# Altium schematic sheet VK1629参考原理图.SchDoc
size A3
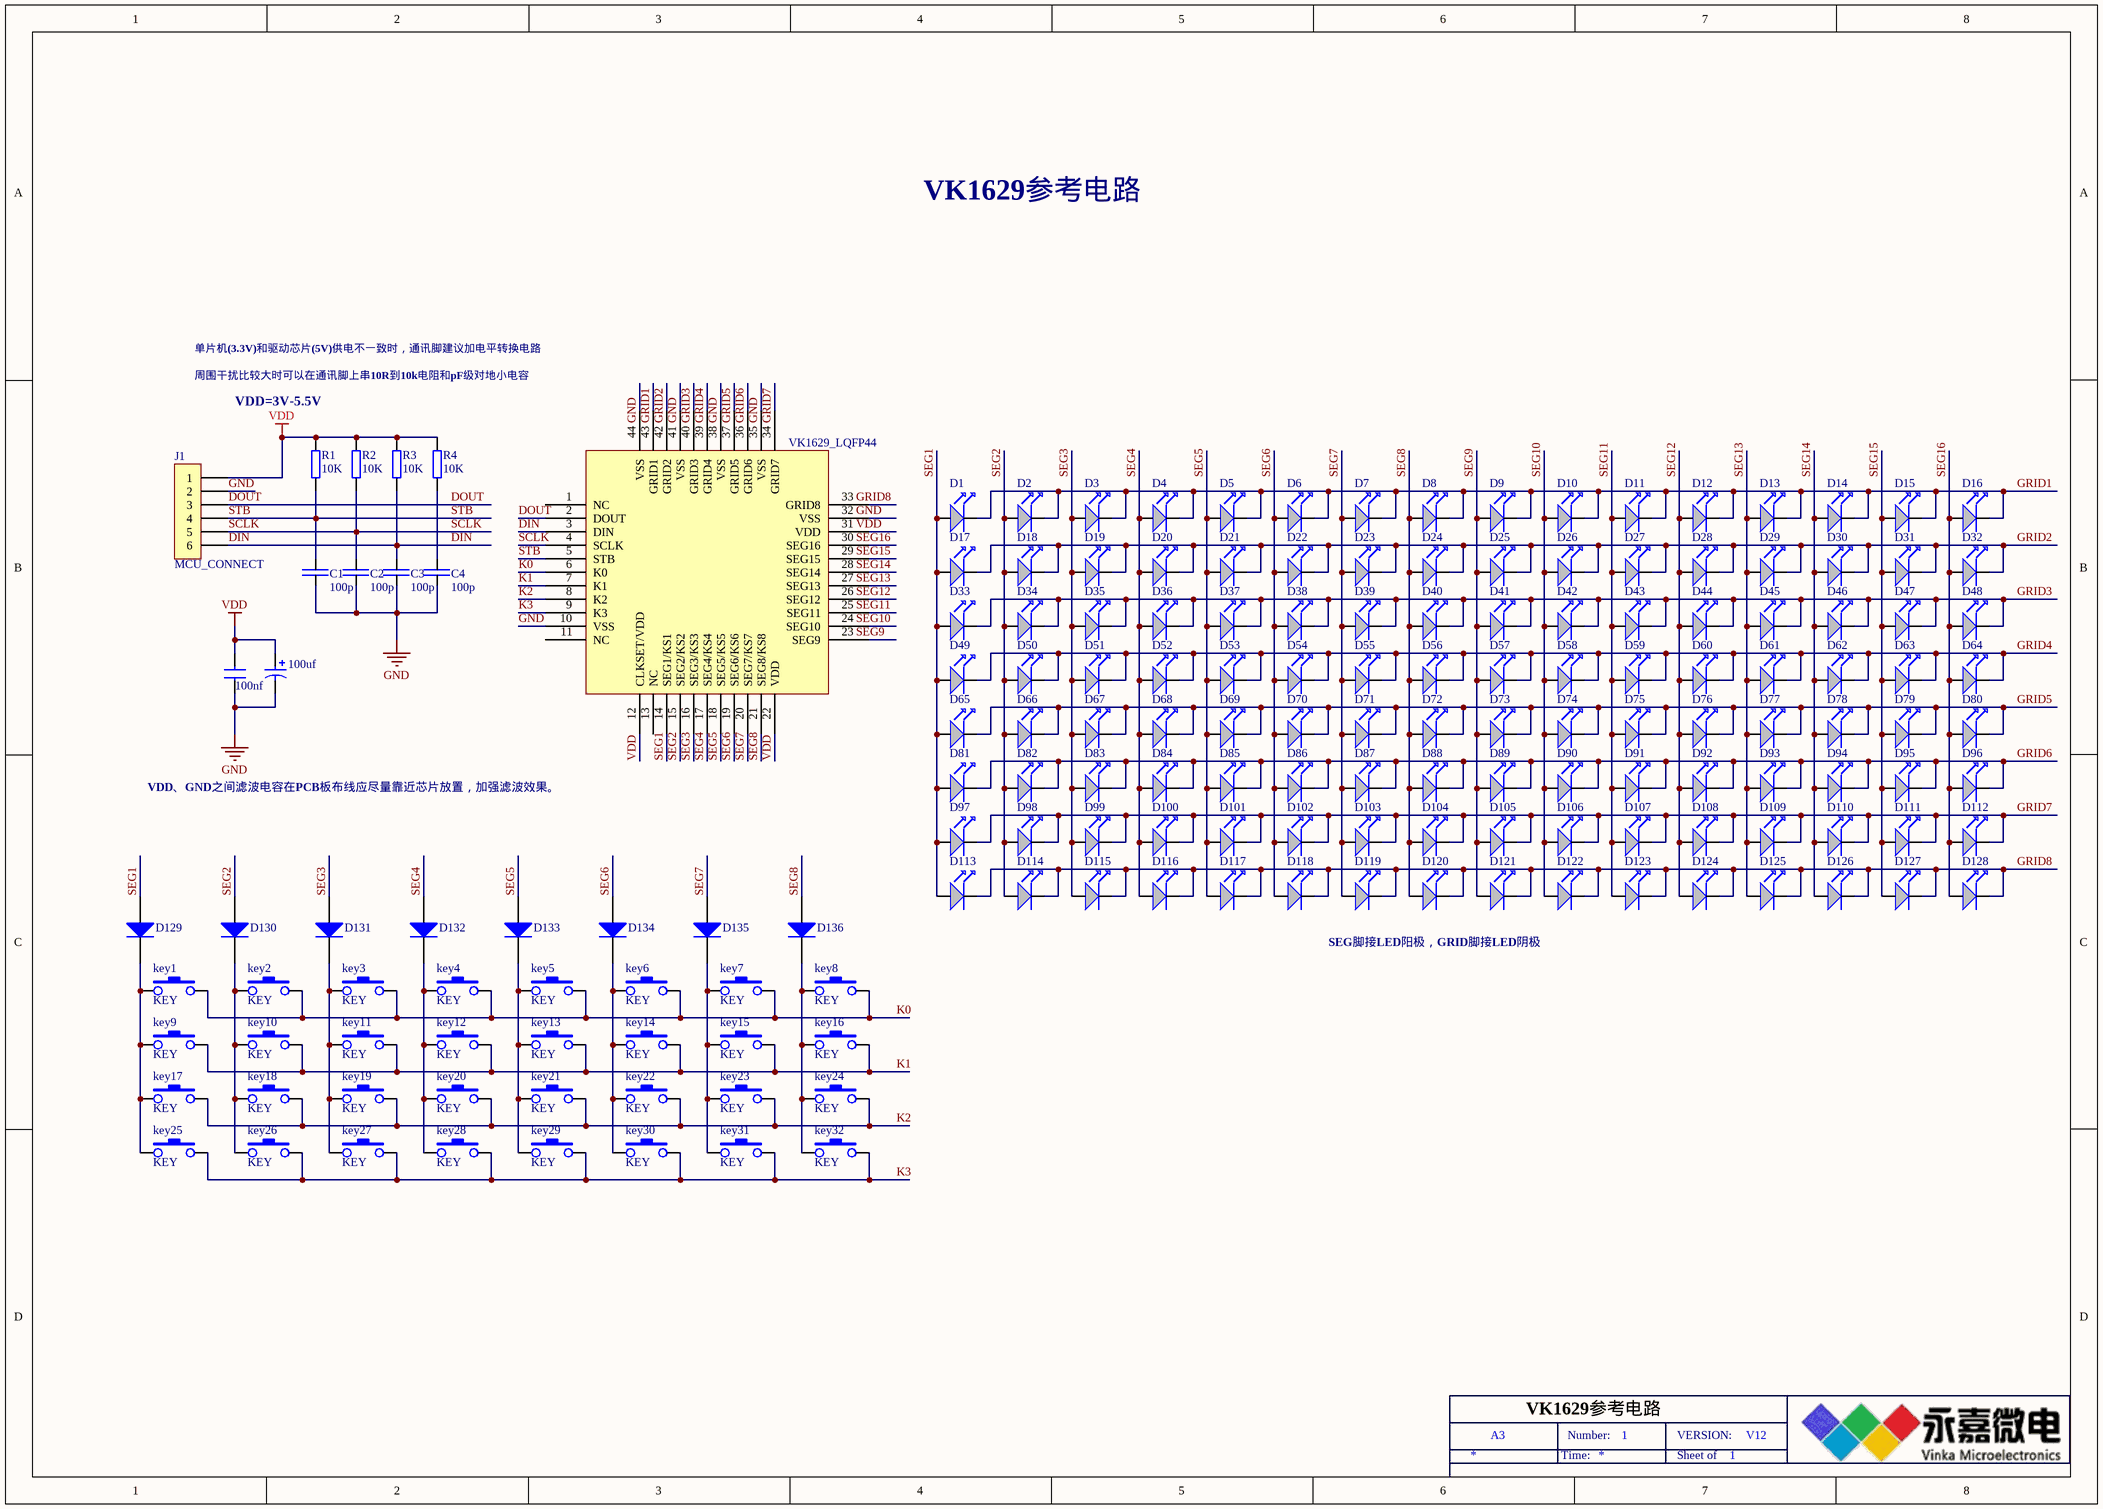
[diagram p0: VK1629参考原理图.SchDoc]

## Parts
1  VK1629_LQFP44
100nf  CAP  (value not drawn)
100uf  CAP2  (value not drawn)
C1  100p  [C0603]
C2  100p  [C0603]
C3  100p  [C0603]
C4  100p  [C0603]
D1  (no value)  [1206-LED]
D2  (no value)  [1206-LED]
D3  (no value)  [1206-LED]
D4  (no value)  [1206-LED]
D5  (no value)  [1206-LED]
D6  (no value)  [1206-LED]
D7  (no value)  [1206-LED]
D8  (no value)  [1206-LED]
D9  (no value)  [1206-LED]
D10  (no value)  [1206-LED]
D11  (no value)  [1206-LED]
D12  (no value)  [1206-LED]
D13  (no value)  [1206-LED]
D14  (no value)  [1206-LED]
D15  (no value)  [1206-LED]
D16  (no value)  [1206-LED]
D17  (no value)  [1206-LED]
D18  (no value)  [1206-LED]
D19  (no value)  [1206-LED]
D20  (no value)  [1206-LED]
D21  (no value)  [1206-LED]
D22  (no value)  [1206-LED]
D23  (no value)  [1206-LED]
D24  (no value)  [1206-LED]
D25  (no value)  [1206-LED]
D26  (no value)  [1206-LED]
D27  (no value)  [1206-LED]
D28  (no value)  [1206-LED]
D29  (no value)  [1206-LED]
D30  (no value)  [1206-LED]
D31  (no value)  [1206-LED]
D32  (no value)  [1206-LED]
D33  (no value)  [1206-LED]
D34  (no value)  [1206-LED]
D35  (no value)  [1206-LED]
D36  (no value)  [1206-LED]
D37  (no value)  [1206-LED]
D38  (no value)  [1206-LED]
D39  (no value)  [1206-LED]
D40  (no value)  [1206-LED]
D41  (no value)  [1206-LED]
D42  (no value)  [1206-LED]
D43  (no value)  [1206-LED]
D44  (no value)  [1206-LED]
D45  (no value)  [1206-LED]
D46  (no value)  [1206-LED]
D47  (no value)  [1206-LED]
D48  (no value)  [1206-LED]
D49  (no value)  [1206-LED]
D50  (no value)  [1206-LED]
D51  (no value)  [1206-LED]
D52  (no value)  [1206-LED]
D53  (no value)  [1206-LED]
D54  (no value)  [1206-LED]
D55  (no value)  [1206-LED]
D56  (no value)  [1206-LED]
D57  (no value)  [1206-LED]
D58  (no value)  [1206-LED]
D59  (no value)  [1206-LED]
D60  (no value)  [1206-LED]
D61  (no value)  [1206-LED]
D62  (no value)  [1206-LED]
D63  (no value)  [1206-LED]
D64  (no value)  [1206-LED]
D65  (no value)  [1206-LED]
D66  (no value)  [1206-LED]
D67  (no value)  [1206-LED]
D68  (no value)  [1206-LED]
D69  (no value)  [1206-LED]
D70  (no value)  [1206-LED]
D71  (no value)  [1206-LED]
D72  (no value)  [1206-LED]
D73  (no value)  [1206-LED]
D74  (no value)  [1206-LED]
D75  (no value)  [1206-LED]
D76  (no value)  [1206-LED]
D77  (no value)  [1206-LED]
D78  (no value)  [1206-LED]
D79  (no value)  [1206-LED]
D80  (no value)  [1206-LED]
D81  (no value)  [1206-LED]
D82  (no value)  [1206-LED]
D83  (no value)  [1206-LED]
D84  (no value)  [1206-LED]
D85  (no value)  [1206-LED]
D86  (no value)  [1206-LED]
D87  (no value)  [1206-LED]
D88  (no value)  [1206-LED]
D89  (no value)  [1206-LED]
D90  (no value)  [1206-LED]
D91  (no value)  [1206-LED]
D92  (no value)  [1206-LED]
D93  (no value)  [1206-LED]
D94  (no value)  [1206-LED]
D95  (no value)  [1206-LED]
D96  (no value)  [1206-LED]
D97  (no value)  [1206-LED]
D98  (no value)  [1206-LED]
D99  (no value)  [1206-LED]
D100  (no value)  [1206-LED]
D101  (no value)  [1206-LED]
D102  (no value)  [1206-LED]
D103  (no value)  [1206-LED]
D104  (no value)  [1206-LED]
D105  (no value)  [1206-LED]
D106  (no value)  [1206-LED]
D107  (no value)  [1206-LED]
D108  (no value)  [1206-LED]
D109  (no value)  [1206-LED]
D110  (no value)  [1206-LED]
D111  (no value)  [1206-LED]
D112  (no value)  [1206-LED]
D113  (no value)  [1206-LED]
D114  (no value)  [1206-LED]
D115  (no value)  [1206-LED]
D116  (no value)  [1206-LED]
D117  (no value)  [1206-LED]
D118  (no value)  [1206-LED]
D119  (no value)  [1206-LED]
D120  (no value)  [1206-LED]
D121  (no value)  [1206-LED]
D122  (no value)  [1206-LED]
D123  (no value)  [1206-LED]
D124  (no value)  [1206-LED]
D125  (no value)  [1206-LED]
D126  (no value)  [1206-LED]
D127  (no value)  [1206-LED]
D128  (no value)  [1206-LED]
D129  Diode 1N4003  [DO-41]  (value not drawn)
D130  Diode 1N4003  [DO-41]  (value not drawn)
D131  Diode 1N4003  [DO-41]  (value not drawn)
D132  Diode 1N4003  [DO-41]  (value not drawn)
D133  Diode 1N4003  [DO-41]  (value not drawn)
D134  Diode 1N4003  [DO-41]  (value not drawn)
D135  Diode 1N4003  [DO-41]  (value not drawn)
D136  Diode 1N4003  [DO-41]  (value not drawn)
J1  MCU_CONNECT
key1  KEY  [AN12]
key2  KEY  [AN12]
key3  KEY  [AN12]
key4  KEY  [AN12]
key5  KEY  [AN12]
key6  KEY  [AN12]
key7  KEY  [AN12]
key8  KEY  [AN12]
key9  KEY  [AN12]
key10  KEY  [AN12]
key11  KEY  [AN12]
key12  KEY  [AN12]
key13  KEY  [AN12]
key14  KEY  [AN12]
key15  KEY  [AN12]
key16  KEY  [AN12]
key17  KEY  [AN12]
key18  KEY  [AN12]
key19  KEY  [AN12]
key20  KEY  [AN12]
key21  KEY  [AN12]
key22  KEY  [AN12]
key23  KEY  [AN12]
key24  KEY  [AN12]
key25  KEY  [AN12]
key26  KEY  [AN12]
key27  KEY  [AN12]
key28  KEY  [AN12]
key29  KEY  [AN12]
key30  KEY  [AN12]
key31  KEY  [AN12]
key32  KEY  [AN12]
R1  10K  [0603-R]
R2  10K  [0603-R]
R3  10K  [0603-R]
R4  10K  [0603-R]

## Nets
GND: 1.10(VSS) 100nf.2 100uf.2 C1.2 C2.2 C3.2 C4.2 J1.2
VDD: 1.12(CLKSET/VDD) 1.22(VDD) 100nf.1 100uf.1 J1.1 R1.1 R2.1 R3.1 R4.1
DIN: 1.3(DIN) C3.1 J1.6 R3.2
DOUT: 1.2(DOUT) J1.3
GRID1: D1.2 D2.2 D3.2 D4.2 D5.2 D6.2 D7.2 D8.2 D9.2 D10.2 D11.2 D12.2 D13.2 D14.2 D15.2 D16.2
GRID2: D17.2 D18.2 D19.2 D20.2 D21.2 D22.2 D23.2 D24.2 D25.2 D26.2 D27.2 D28.2 D29.2 D30.2 D31.2 D32.2
GRID3: D33.2 D34.2 D35.2 D36.2 D37.2 D38.2 D39.2 D40.2 D41.2 D42.2 D43.2 D44.2 D45.2 D46.2 D47.2 D48.2
GRID4: D49.2 D50.2 D51.2 D52.2 D53.2 D54.2 D55.2 D56.2 D57.2 D58.2 D59.2 D60.2 D61.2 D62.2 D63.2 D64.2
GRID5: D65.2 D66.2 D67.2 D68.2 D69.2 D70.2 D71.2 D72.2 D73.2 D74.2 D75.2 D76.2 D77.2 D78.2 D79.2 D80.2
GRID6: D81.2 D82.2 D83.2 D84.2 D85.2 D86.2 D87.2 D88.2 D89.2 D90.2 D91.2 D92.2 D93.2 D94.2 D95.2 D96.2
GRID7: D97.2 D98.2 D99.2 D100.2 D101.2 D102.2 D103.2 D104.2 D105.2 D106.2 D107.2 D108.2 D109.2 D110.2 D111.2 D112.2
GRID8: D113.2 D114.2 D115.2 D116.2 D117.2 D118.2 D119.2 D120.2 D121.2 D122.2 D123.2 D124.2 D125.2 D126.2 D127.2 D128.2
K0: 1.6(K0) key1.2 key2.2 key3.2 key4.2 key5.2 key6.2 key7.2 key8.2
K1: 1.7(K1) key9.2 key10.2 key11.2 key12.2 key13.2 key14.2 key15.2 key16.2
K2: 1.8(K2) key17.2 key18.2 key19.2 key20.2 key21.2 key22.2 key23.2 key24.2
K3: 1.9(K3) key25.2 key26.2 key27.2 key28.2 key29.2 key30.2 key31.2 key32.2
SCLK: 1.4(SCLK) C2.1 J1.5 R2.2
SEG1: 1.14(SEG1/KS1) D1.1 D17.1 D33.1 D49.1 D65.1 D81.1 D97.1 D113.1 D129.1(A)
SEG2: 1.15(SEG2/KS2) D2.1 D18.1 D34.1 D50.1 D66.1 D82.1 D98.1 D114.1 D130.1(A)
SEG3: 1.16(SEG3/KS3) D3.1 D19.1 D35.1 D51.1 D67.1 D83.1 D99.1 D115.1 D131.1(A)
SEG4: 1.17(SEG4/KS4) D4.1 D20.1 D36.1 D52.1 D68.1 D84.1 D100.1 D116.1 D132.1(A)
SEG5: 1.18(SEG5/KS5) D5.1 D21.1 D37.1 D53.1 D69.1 D85.1 D101.1 D117.1 D133.1(A)
SEG6: 1.19(SEG6/KS6) D6.1 D22.1 D38.1 D54.1 D70.1 D86.1 D102.1 D118.1 D134.1(A)
SEG7: 1.20(SEG7/KS7) D7.1 D23.1 D39.1 D55.1 D71.1 D87.1 D103.1 D119.1 D135.1(A)
SEG8: 1.21(SEG8/KS8) D8.1 D24.1 D40.1 D56.1 D72.1 D88.1 D104.1 D120.1 D136.1(A)
SEG9: D9.1 D25.1 D41.1 D57.1 D73.1 D89.1 D105.1 D121.1
SEG10: D10.1 D26.1 D42.1 D58.1 D74.1 D90.1 D106.1 D122.1
SEG11: D11.1 D27.1 D43.1 D59.1 D75.1 D91.1 D107.1 D123.1
SEG12: D12.1 D28.1 D44.1 D60.1 D76.1 D92.1 D108.1 D124.1
SEG13: D13.1 D29.1 D45.1 D61.1 D77.1 D93.1 D109.1 D125.1
SEG14: D14.1 D30.1 D46.1 D62.1 D78.1 D94.1 D110.1 D126.1
SEG15: D15.1 D31.1 D47.1 D63.1 D79.1 D95.1 D111.1 D127.1
SEG16: D16.1 D32.1 D48.1 D64.1 D80.1 D96.1 D112.1 D128.1
STB: 1.5(STB) C1.1 J1.4 R1.2
NetC4_1: C4.1 R4.2
NetD129_2: D129.2(K) key1.1 key9.1 key17.1 key25.1
NetD130_2: D130.2(K) key2.1 key10.1 key18.1 key26.1
NetD131_2: D131.2(K) key3.1 key11.1 key19.1 key27.1
NetD132_2: D132.2(K) key4.1 key12.1 key20.1 key28.1
NetD133_2: D133.2(K) key5.1 key13.1 key21.1 key29.1
NetD134_2: D134.2(K) key6.1 key14.1 key22.1 key30.1
NetD135_2: D135.2(K) key7.1 key15.1 key23.1 key31.1
NetD136_2: D136.2(K) key8.1 key16.1 key24.1 key32.1

Not connected (* = marked no-connect by the designer): 1 1(NC) 11(NC) 13(NC) 23(SEG9) 24(SEG10) 25(SEG11) 26(SEG12) 27(SEG13) 28(SEG14) 29(SEG15) 30(SEG16) 31(VDD) 32(VSS) 33(GRID8) 34(GRID7) 35(VSS) 36(GRID6) 37(GRID5) 38(VSS) 39(GRID4) 40(GRID3) 41(VSS) 42(GRID2) 43(GRID1) 44(VSS)

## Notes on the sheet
- VK1629参考电路
- 周围干扰比较大时可以在通讯脚上串10R到10k电阻和pF级对地小电容
- 单片机(3.3V)和驱动芯片(5V)供电不一致时，通讯脚建议加电平转换电路
- VDD=3V-5.5V
- VDD、GND之间滤波电容在PCB板布线应尽量靠近芯片放置，加强滤波效果。
- SEG脚接LED阳极，GRID脚接LED阴极
- A3
- Time:
- Number:
- 1
- Sheet of
- VERSION:
- V12
- Labels drawn without touching a wire or pin: GND, GRID1, GRID2, GRID3, GRID4, GRID5, GRID6, GRID7, GRID8, SEG9, SEG10, SEG11, SEG12, SEG13, SEG14, SEG15, SEG16, VDD

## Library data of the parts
1 = VK1629
100nf = CAP: Capacitor
100uf = CAP2: Bi-Polar Capacitor
C1-C4 = CAP: 分类: 电容; 参数: 20%,50V,X5R
D1-D128 = LED: Text Field1: 30; Text Field2: 20
D129-D136 = Diode 1N4003: 1 Amp General Purpose Rectifier
J1 = CON6: Connector
R1-R4 = RES: Resistor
